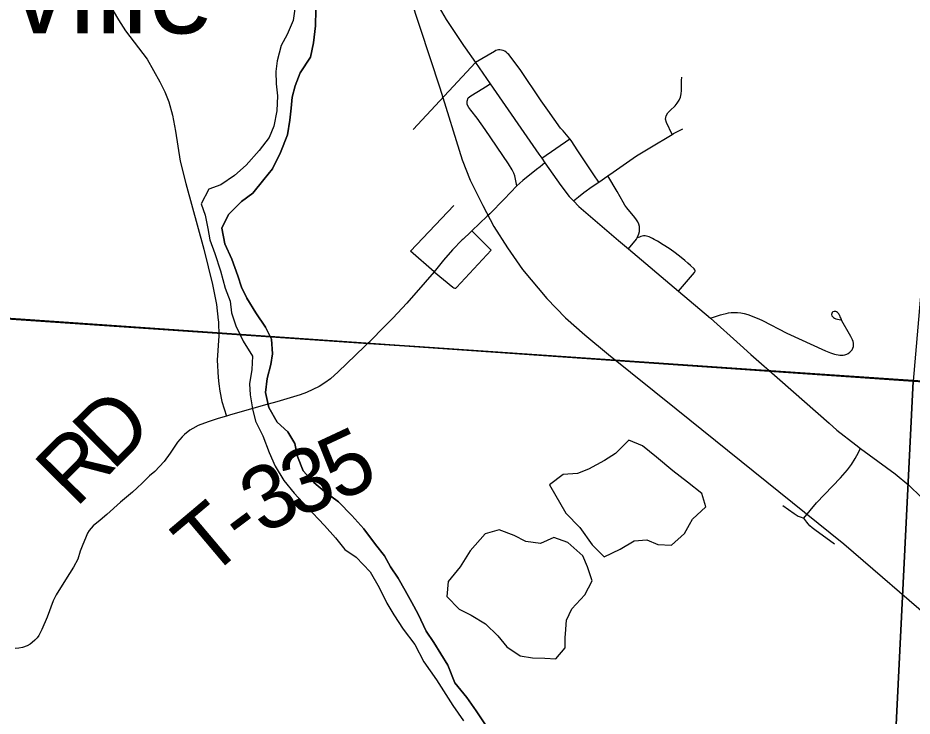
# Model space of a CAD drawing. Extents: x 0 to 34, y 0 to 22.
# Drawn here: x 6.717 to 7.515, y 18.417 to 19.04 of the extents above; entities that cross this region are included whole.
import ezdxf

# ---------------------------------------------------------------- set-up
doc = ezdxf.new("R2010")
doc.units = 0
for name, color, linetype in [('GM_X_Corporation', 7, 'Continuous'), ('GM_X_County_Road', 7, 'Continuous'), ('GM_X_Major_River', 7, 'Continuous'), ('GM_X_Minor_Lake', 7, 'Continuous'), ('GM_X_Rail_Line', 7, 'Continuous'), ('GM_X_Township_Road', 7, 'Continuous'), ('GM_X_Township_Road_Text', 7, 'Continuous'), ('GM_X_Township_Text', 7, 'Continuous'), ('GM_X_Unincorporated_Text', 7, 'Continuous')]:
    doc.layers.add(name, color=color, linetype=linetype)

msp = doc.modelspace()

# ---------------------------------------------------------------- linework, layer by layer
at = {"layer": 'GM_X_Corporation'}
for points in [[(8.9, 18.63104), (8.9, 20.9), (3.64766, 20.9), (3.64639, 20.88271), (3.56651, 19.79699), (3.56604, 19.79055), (3.50701, 18.98834), (4.29309, 18.93502), (4.42098, 18.92635), (4.43616, 18.92532), (5.60032, 18.84635), (6.4706, 18.78732), (6.89502, 18.75853), (7.02554, 18.74968), (7.07142, 18.74657), (7.08445, 18.74568), (7.38896, 18.72502), (7.80881, 18.69655), (7.83532, 18.69516)], [(6.57976, 19.81144), (7.59407, 19.75829), (7.59584, 19.63858), (7.51615, 18.71572), (6.53912, 18.78352)], [(7.51615, 18.71572), (7.4643, 17.67029), (6.43864, 17.7441), (6.53912, 18.78352)], [(8.55257, 18.64968), (8.46287, 17.60104), (7.4643, 17.67029), (7.51615, 18.71572)]]:
    msp.add_lwpolyline(points, close=True, dxfattribs=at)
at = {"layer": 'GM_X_County_Road'}
for points in [[(7.09309, 19.04928), (7.09919, 19.03857), (7.11473, 19.01536), (7.11628, 19.01312), (7.1254, 18.99998), (7.13844, 18.98119), (7.18206, 18.91832), (7.18457, 18.91469), (7.18745, 18.91056), (7.20154, 18.89027), (7.20917, 18.88054), (7.21289, 18.87664), (7.21767, 18.87163), (7.25298, 18.84127), (7.26189, 18.83372), (7.30648, 18.79601), (7.33504, 18.77185), (7.36152, 18.74818), (7.37124, 18.73962), (7.39692, 18.71698)], [(7.39692, 18.71698), (7.44094, 18.67818), (7.44777, 18.67216), (7.46496, 18.65891), (7.46914, 18.65583), (7.49998, 18.63304), (7.512, 18.6231), (7.52321, 18.61225), (7.5399, 18.59374), (7.59634, 18.52742), (7.60398, 18.51724), (7.60691, 18.51305), (7.62242, 18.48872), (7.64954, 18.44339), (7.65833, 18.43067), (7.66812, 18.41872), (7.68735, 18.3985), (7.69979, 18.38557), (7.71323, 18.37161), (7.73813, 18.34329), (7.74385, 18.33657), (7.75408, 18.32513), (7.76217, 18.31591), (7.78442, 18.29052)]]:
    msp.add_lwpolyline(points, dxfattribs=at)
at = {"layer": 'GM_X_Major_River'}
for p, q in [((6.96429, 19.04795), (6.96287, 19.03771)), ((6.98258, 19.03296), (6.98284, 19.04698)), ((6.96287, 19.03771), (6.9573, 19.02515)), ((6.98082, 19.01778), (6.98258, 19.03296)), ((6.9573, 19.02515), (6.95209, 19.01525)), ((6.95209, 19.01525), (6.94842, 19.00157)), ((6.97829, 19.00488), (6.98082, 19.01778)), ((6.94842, 19.00157), (6.94737, 18.99209)), ((6.96895, 18.99077), (6.97829, 19.00488)), ((6.94737, 18.99209), (6.94747, 18.9811)), ((6.96451, 18.97936), (6.96895, 18.99077)), ((6.94747, 18.9811), (6.94869, 18.9705)), ((6.96195, 18.96911), (6.96451, 18.97936)), ((6.94869, 18.9705), (6.94806, 18.95685)), ((6.9609, 18.95924), (6.96195, 18.96911)), ((6.94806, 18.95685), (6.94553, 18.94319)), ((6.95986, 18.94862), (6.9609, 18.95924)), ((6.9577, 18.93572), (6.95986, 18.94862)), ((6.94553, 18.94319), (6.94145, 18.9333)), ((6.95141, 18.91975), (6.9577, 18.93572)), ((6.94145, 18.9333), (6.93247, 18.92147)), ((6.93247, 18.92147), (6.92086, 18.90848)), ((6.94434, 18.90528), (6.95141, 18.91975)), ((6.92086, 18.90848), (6.91034, 18.89929)), ((6.93648, 18.89574), (6.94434, 18.90528)), ((6.91034, 18.89929), (6.89831, 18.89084)), ((6.92675, 18.88352), (6.93648, 18.89574)), ((6.89831, 18.89084), (6.88737, 18.88695)), ((6.88737, 18.88695), (6.88067, 18.87401)), ((6.9166, 18.87623), (6.92675, 18.88352)), ((6.88067, 18.87401), (6.88417, 18.86381)), ((6.90497, 18.86438), (6.9166, 18.87623)), ((6.88417, 18.86381), (6.88654, 18.85208)), ((6.89902, 18.8522), (6.90497, 18.86438)), ((6.88654, 18.85208), (6.88852, 18.84187)), ((6.90179, 18.8382), (6.89902, 18.8522)), ((6.88852, 18.84187), (6.89279, 18.82978)), ((6.90797, 18.82461), (6.90179, 18.8382)), ((6.89279, 18.82978), (6.89784, 18.81429)), ((6.91339, 18.80989), (6.90797, 18.82461)), ((6.89784, 18.81429), (6.90214, 18.79879)), ((6.91651, 18.79968), (6.91339, 18.80989)), ((6.90214, 18.79879), (6.9064, 18.78708)), ((6.92151, 18.78987), (6.91651, 18.79968)), ((6.9064, 18.78708), (6.90763, 18.77686)), ((6.92957, 18.77668), (6.92151, 18.78987)), ((6.90763, 18.77686), (6.91151, 18.76515)), ((6.93801, 18.76388), (6.92957, 18.77668)), ((6.91151, 18.76515), (6.91806, 18.75157)), ((6.9434, 18.75332), (6.93801, 18.76388)), ((6.94427, 18.74006), (6.9434, 18.75332)), ((6.91806, 18.75157), (6.9265, 18.73801)), ((6.9265, 18.73801), (6.92585, 18.72625)), ((6.94284, 18.73057), (6.94427, 18.74006)), ((6.93954, 18.71804), (6.94284, 18.73057)), ((6.92585, 18.72625), (6.92369, 18.71335)), ((6.92369, 18.71335), (6.92453, 18.7035)), ((6.93814, 18.70552), (6.93954, 18.71804)), ((6.9409, 18.69228), (6.93814, 18.70552)), ((6.92453, 18.7035), (6.92654, 18.69102)), ((6.92654, 18.69102), (6.92928, 18.68005)), ((6.94859, 18.67909), (6.9409, 18.69228)), ((6.92928, 18.68005), (6.93583, 18.66685)), ((6.95812, 18.67046), (6.94859, 18.67909)), ((6.93583, 18.66685), (6.94125, 18.65212)), ((6.96426, 18.66029), (6.95812, 18.67046)), ((6.96663, 18.64856), (6.96426, 18.66029)), ((6.94125, 18.65212), (6.94665, 18.64004)), ((6.97167, 18.63572), (6.96663, 18.64856)), ((6.94665, 18.64004), (6.95433, 18.62723)), ((6.98121, 18.6252), (6.97167, 18.63572)), ((6.95433, 18.62723), (6.96351, 18.61594)), ((6.99074, 18.61733), (6.98121, 18.6252)), ((7.00331, 18.60797), (6.99074, 18.61733)), ((6.96351, 18.61594), (6.97497, 18.60354)), ((6.97497, 18.60354), (6.99063, 18.58701)), ((7.01514, 18.59595), (7.00331, 18.60797)), ((7.02584, 18.58392), (7.01514, 18.59595)), ((6.99063, 18.58701), (7.00056, 18.57611)), ((7.03618, 18.56999), (7.02584, 18.58392)), ((7.00056, 18.57611), (7.00898, 18.56558)), ((7.04421, 18.55984), (7.03618, 18.56999)), ((7.00898, 18.56558), (7.01887, 18.55885)), ((7.01887, 18.55885), (7.03147, 18.5457)), ((7.0496, 18.55003), (7.04421, 18.55984)), ((7.03147, 18.5457), (7.03954, 18.53175)), ((7.0565, 18.53986), (7.0496, 18.55003)), ((7.06265, 18.52893), (7.0565, 18.53986)), ((7.03954, 18.53175), (7.04647, 18.51779)), ((7.06879, 18.51838), (7.06265, 18.52893)), ((7.04647, 18.51779), (7.05262, 18.50724)), ((7.07418, 18.50782), (7.06879, 18.51838)), ((7.05262, 18.50724), (7.06106, 18.49443)), ((7.0815, 18.49272), (7.07418, 18.50782)), ((7.06106, 18.49443), (7.07139, 18.48089)), ((7.0884, 18.48256), (7.0815, 18.49272)), ((7.07139, 18.48089), (7.07947, 18.46542)), ((7.10069, 18.46221), (7.0884, 18.48256)), ((7.07947, 18.46542), (7.09058, 18.44923)), ((7.10688, 18.44672), (7.10069, 18.46221)), ((7.09058, 18.44923), (7.09902, 18.43604)), ((7.11759, 18.43356), (7.10688, 18.44672)), ((7.09902, 18.43604), (7.10516, 18.42625)), ((7.12601, 18.42151), (7.11759, 18.43356)), ((7.10516, 18.42625), (7.11474, 18.41269)), ((7.13483, 18.40833), (7.12601, 18.42151))]:
    msp.add_line(p, q, dxfattribs=at)
for points in [[(6.96429, 19.04795), (6.96287, 19.03771), (6.9573, 19.02515), (6.95209, 19.01525), (6.94842, 19.00157)], [(6.98284, 19.04698), (6.98258, 19.03296), (6.98082, 19.01778), (6.97829, 19.00488), (6.96895, 18.99077)], [(6.94842, 19.00157), (6.94737, 18.99209), (6.94747, 18.9811), (6.94869, 18.9705), (6.94806, 18.95685), (6.94553, 18.94319), (6.94145, 18.9333), (6.93247, 18.92147), (6.92086, 18.90848), (6.91034, 18.89929), (6.89831, 18.89084), (6.88737, 18.88695), (6.88067, 18.87401), (6.88417, 18.86381), (6.88654, 18.85208), (6.88852, 18.84187), (6.89279, 18.82978), (6.89784, 18.81429), (6.90214, 18.79879), (6.9064, 18.78708), (6.90763, 18.77686), (6.91151, 18.76515), (6.91806, 18.75157), (6.9265, 18.73801), (6.92585, 18.72625), (6.92369, 18.71335), (6.92453, 18.7035), (6.92654, 18.69102), (6.92928, 18.68005), (6.93583, 18.66685), (6.94125, 18.65212), (6.94665, 18.64004), (6.95433, 18.62723), (6.96351, 18.61594), (6.97497, 18.60354), (6.99063, 18.58701), (7.00056, 18.57611), (7.00898, 18.56558), (7.01887, 18.55885), (7.03147, 18.5457), (7.03954, 18.53175), (7.04647, 18.51779), (7.05262, 18.50724), (7.06106, 18.49443), (7.07139, 18.48089), (7.07947, 18.46542), (7.09058, 18.44923), (7.09902, 18.43604), (7.10516, 18.42625), (7.11474, 18.41269)], [(6.96895, 18.99077), (6.96451, 18.97936), (6.96195, 18.96911), (6.9609, 18.95924), (6.95986, 18.94862), (6.9577, 18.93572), (6.95141, 18.91975), (6.94434, 18.90528), (6.93648, 18.89574), (6.92675, 18.88352), (6.9166, 18.87623), (6.90497, 18.86438), (6.89902, 18.8522), (6.90179, 18.8382), (6.90797, 18.82461), (6.91339, 18.80989), (6.91651, 18.79968), (6.92151, 18.78987), (6.92957, 18.77668), (6.93801, 18.76388), (6.9434, 18.75332), (6.94427, 18.74006), (6.94284, 18.73057), (6.93954, 18.71804), (6.93814, 18.70552), (6.9409, 18.69228), (6.94859, 18.67909), (6.95812, 18.67046), (6.96426, 18.66029), (6.96663, 18.64856), (6.97167, 18.63572), (6.98121, 18.6252), (6.99074, 18.61733), (7.00331, 18.60797), (7.01514, 18.59595), (7.02584, 18.58392), (7.03618, 18.56999), (7.04421, 18.55984), (7.0496, 18.55003), (7.0565, 18.53986), (7.06265, 18.52893), (7.06879, 18.51838), (7.07418, 18.50782), (7.0815, 18.49272), (7.0884, 18.48256), (7.10069, 18.46221), (7.10688, 18.44672), (7.11759, 18.43356), (7.12601, 18.42151), (7.13483, 18.40833)]]:
    msp.add_lwpolyline(points, dxfattribs=at)
at = {"layer": 'GM_X_Minor_Lake'}
for p, q in [((7.26239, 18.663), (7.25039, 18.65115)), ((7.27454, 18.65819), (7.26239, 18.663)), ((7.28712, 18.64807), (7.27454, 18.65819)), ((7.25039, 18.65115), (7.2406, 18.645)), ((7.2406, 18.645), (7.22629, 18.63729)), ((7.3016, 18.6357), (7.28712, 18.64807)), ((7.20363, 18.63253), (7.1916, 18.62333)), ((7.21649, 18.63341), (7.20363, 18.63253)), ((7.22629, 18.63729), (7.21649, 18.63341)), ((7.31456, 18.62559), (7.3016, 18.6357)), ((7.32751, 18.61547), (7.31456, 18.62559)), ((7.1916, 18.62333), (7.2062, 18.59807)), ((7.33102, 18.60376), (7.32751, 18.61547)), ((7.31901, 18.59266), (7.33102, 18.60376)), ((7.2062, 18.59807), (7.21842, 18.5853)), ((7.31635, 18.5878), (7.31901, 18.59266)), ((7.21842, 18.5853), (7.22953, 18.56986)), ((7.31193, 18.57971), (7.31635, 18.5878)), ((7.13409, 18.5796), (7.12061, 18.56432)), ((7.14655, 18.58313), (7.13409, 18.5796)), ((7.15984, 18.57794), (7.14655, 18.58313)), ((7.17048, 18.57274), (7.15984, 18.57794)), ((7.19542, 18.57637), (7.18336, 18.57096)), ((7.20795, 18.57194), (7.19542, 18.57637)), ((7.30029, 18.56937), (7.31193, 18.57971)), ((7.18336, 18.57096), (7.17048, 18.57274)), ((7.22129, 18.55994), (7.20795, 18.57194)), ((7.22953, 18.56986), (7.24022, 18.55897)), ((7.25454, 18.56592), (7.26696, 18.57324)), ((7.26696, 18.57324), (7.2783, 18.5741)), ((7.2783, 18.5741), (7.28818, 18.57002)), ((7.28818, 18.57002), (7.30029, 18.56937)), ((7.12061, 18.56432), (7.11165, 18.55022)), ((7.24022, 18.55897), (7.25454, 18.56592)), ((7.22554, 18.55012), (7.22129, 18.55994)), ((7.11165, 18.55022), (7.10117, 18.53686)), ((7.22943, 18.53765), (7.22554, 18.55012)), ((7.10117, 18.53686), (7.09977, 18.52359)), ((7.22311, 18.52509), (7.22943, 18.53765)), ((7.09977, 18.52359), (7.11084, 18.51232)), ((7.21149, 18.51248), (7.22311, 18.52509)), ((7.11084, 18.51232), (7.12148, 18.50711)), ((7.12148, 18.50711), (7.13442, 18.49927)), ((7.20666, 18.50258), (7.21149, 18.51248)), ((7.13442, 18.49927), (7.14548, 18.48838)), ((7.20563, 18.49045), (7.20666, 18.50258)), ((7.20555, 18.48702), (7.20563, 18.49045)), ((7.14548, 18.48838), (7.15352, 18.4786)), ((7.20536, 18.47794), (7.20555, 18.48702)), ((7.15352, 18.4786), (7.16531, 18.47075)), ((7.19712, 18.46801), (7.20536, 18.47794)), ((7.16531, 18.47075), (7.1763, 18.46896)), ((7.1763, 18.46896), (7.18728, 18.46868)), ((7.18728, 18.46868), (7.19712, 18.46801))]:
    msp.add_line(p, q, dxfattribs=at)
at = {"layer": 'GM_X_Rail_Line'}
msp.add_lwpolyline([(6.98662, 19.30256), (7.09368, 18.9774), (7.11355, 18.91342), (7.12056, 18.89504), (7.13192, 18.8725), (7.14183, 18.85389), (7.15398, 18.83476), (7.1673, 18.81542), (7.18918, 18.78941), (7.20588, 18.7724), (7.2229, 18.75718), (7.24425, 18.73963), (7.30439, 18.69111), (7.45417, 18.57062), (7.53827, 18.49802)], dxfattribs=at)
at = {"layer": 'GM_X_Township_Road'}
msp.add_line((7.06989, 18.94023), (7.1254, 18.99998), dxfattribs=at)
for points in [[(6.79658, 19.05606), (6.80704, 19.03811), (6.81312, 19.02851), (6.83249, 19.00318), (6.8438, 18.98288), (6.84829, 18.97389), (6.85176, 18.96512), (6.85513, 18.95324), (6.85784, 18.93871), (6.86199, 18.91219), (6.86692, 18.89202), (6.88295, 18.83345), (6.89091, 18.80193), (6.89431, 18.78419), (6.89588, 18.77028), (6.89608, 18.76857), (6.89643, 18.75616), (6.89505, 18.73458), (6.89583, 18.71909), (6.89649, 18.71342)], [(7.18457, 18.91469), (7.20951, 18.93191), (7.20354, 18.9392), (7.20139, 18.94148), (7.1901, 18.9575), (7.18419, 18.96582), (7.16539, 18.99391), (7.15513, 19.00714), (7.15407, 19.00825), (7.1529, 19.00927), (7.15157, 19.01015), (7.15004, 19.0108), (7.14853, 19.01125), (7.14724, 19.01144), (7.14597, 19.01148), (7.14481, 19.01125), (7.14367, 19.01075), (7.14234, 19.01005), (7.1254, 18.99998)], [(7.30102, 18.93602), (7.29578, 18.94665), (7.29512, 18.94962), (7.29559, 18.95257), (7.29717, 18.95515), (7.2992, 18.9574), (7.30358, 18.96159), (7.30553, 18.96387), (7.30709, 18.96644), (7.30826, 18.9692), (7.30895, 18.97212), (7.30919, 18.97511), (7.30931, 18.98414), (7.30952, 18.98715)], [(7.16245, 18.89016), (7.16054, 18.89885), (7.15966, 18.9013), (7.15808, 18.90446), (7.15488, 18.90971), (7.13404, 18.94025), (7.12699, 18.95032), (7.12118, 18.9575), (7.11943, 18.96004), (7.11815, 18.96276), (7.11791, 18.9657), (7.11901, 18.96854), (7.12134, 18.97053), (7.13186, 18.97694), (7.13435, 18.97855), (7.13844, 18.98119)], [(7.21289, 18.87664), (7.21728, 18.88025), (7.22205, 18.88419), (7.22968, 18.88946), (7.23539, 18.89341), (7.24347, 18.89902), (7.24819, 18.90226), (7.26922, 18.91694), (7.28095, 18.92398), (7.30102, 18.93602), (7.30215, 18.93671), (7.30761, 18.93959), (7.3104, 18.9409)], [(7.23539, 18.89341), (7.23098, 18.89983), (7.21672, 18.92116), (7.21085, 18.9304), (7.20951, 18.93191)], [(7.18745, 18.91056), (7.1831, 18.90713), (7.1799, 18.90459), (7.16773, 18.89492), (7.16245, 18.89016), (7.15103, 18.87825), (7.13813, 18.86507)], [(7.26189, 18.83372), (7.26901, 18.84252), (7.26977, 18.84368), (7.27129, 18.8473), (7.27169, 18.84943), (7.27189, 18.85181), (7.27169, 18.85393), (7.27124, 18.85591), (7.27027, 18.85803), (7.26921, 18.85975), (7.26769, 18.86188), (7.26046, 18.87048), (7.25871, 18.87283), (7.25718, 18.87536), (7.25173, 18.88497), (7.24347, 18.89902)], [(7.08843, 18.81339), (7.06758, 18.83165), (7.10606, 18.87244)], [(7.13813, 18.86507), (7.13598, 18.86287), (7.12221, 18.84986), (7.12093, 18.84865), (7.11438, 18.84246)], [(7.08843, 18.81339), (7.10524, 18.79978), (7.10624, 18.79896), (7.10696, 18.79861), (7.10798, 18.7987), (7.10865, 18.79921), (7.13957, 18.83262), (7.12223, 18.84983)], [(7.11438, 18.84246), (7.11365, 18.84178), (7.10501, 18.83302), (7.0968, 18.8238), (7.08843, 18.81339), (7.08069, 18.80415), (7.06433, 18.78552), (7.05162, 18.77187), (7.04196, 18.76216)], [(7.30648, 18.79601), (7.32093, 18.81259), (7.32132, 18.81323), (7.32144, 18.81388), (7.32134, 18.81454), (7.32107, 18.81516), (7.32049, 18.81598), (7.31736, 18.81906), (7.31507, 18.82106), (7.31211, 18.82352), (7.30737, 18.82724), (7.30237, 18.83108), (7.29815, 18.83412), (7.29288, 18.83757), (7.28784, 18.84057), (7.28487, 18.84227), (7.28328, 18.84312), (7.28208, 18.84375), (7.28051, 18.84447), (7.27929, 18.84493), (7.27796, 18.84526), (7.27677, 18.84542), (7.2755, 18.84542), (7.27424, 18.84523), (7.27302, 18.84487), (7.27178, 18.84434), (7.26977, 18.84368)], [(7.33504, 18.77185), (7.34406, 18.77488), (7.34654, 18.77561), (7.34919, 18.77629), (7.35132, 18.77671), (7.35367, 18.77697), (7.3567, 18.77714), (7.3593, 18.7771), (7.36216, 18.77684), (7.36511, 18.7762), (7.36835, 18.77518), (7.37831, 18.77134), (7.38152, 18.76993), (7.40315, 18.75872), (7.43769, 18.74285), (7.44237, 18.741), (7.44585, 18.73992), (7.44732, 18.73953), (7.44898, 18.73918), (7.45045, 18.73899), (7.45186, 18.7389), (7.45341, 18.73896), (7.45492, 18.73913), (7.45668, 18.73976), (7.45808, 18.74056), (7.45955, 18.74164), (7.46078, 18.74277), (7.46169, 18.74386), (7.46229, 18.74514), (7.46266, 18.7467), (7.46274, 18.74805), (7.46262, 18.74953), (7.46233, 18.75115), (7.4619, 18.75257), (7.46129, 18.75397), (7.46038, 18.7556), (7.45914, 18.75779), (7.45228, 18.76974), (7.45192, 18.77058), (7.45164, 18.77137), (7.45133, 18.77223), (7.45099, 18.77317), (7.45053, 18.77425), (7.4501, 18.77505), (7.4496, 18.77578), (7.44909, 18.77637), (7.44856, 18.77692), (7.4477, 18.77759), (7.44705, 18.77783), (7.44648, 18.77798), (7.44539, 18.778), (7.4444, 18.77757), (7.44376, 18.77692), (7.4434, 18.77619), (7.44327, 18.77517), (7.4435, 18.7742), (7.44398, 18.77341), (7.44478, 18.77254), (7.44577, 18.7719), (7.44709, 18.77133), (7.44837, 18.77097), (7.44994, 18.77075), (7.4514, 18.77061)], [(7.04196, 18.76216), (7.04127, 18.76147), (7.03413, 18.75428), (7.00297, 18.72405), (6.99595, 18.71796), (6.99098, 18.71431), (6.98584, 18.71112), (6.9804, 18.70826)], [(6.89649, 18.71342), (6.89725, 18.70679), (6.8991, 18.69771), (6.9032, 18.68465)], [(6.9804, 18.70826), (6.97474, 18.70577), (6.9689, 18.70365), (6.94813, 18.69741), (6.93606, 18.69403), (6.90587, 18.68541), (6.9032, 18.68465), (6.89582, 18.68254), (6.8868, 18.67959), (6.87796, 18.67614), (6.87314, 18.6736), (6.87057, 18.67193), (6.86577, 18.66815), (6.86357, 18.66603), (6.8615, 18.66377), (6.85959, 18.66133), (6.85303, 18.6516), (6.84764, 18.64413), (6.8436, 18.63949), (6.83928, 18.63511), (6.8346, 18.63118), (6.82789, 18.62471), (6.82356, 18.62053), (6.81942, 18.61685), (6.80882, 18.60768), (6.79663, 18.59683), (6.79041, 18.59165), (6.78437, 18.58682), (6.78068, 18.58242), (6.77918, 18.58001), (6.7779, 18.57727), (6.77436, 18.56842), (6.7728, 18.56398), (6.77052, 18.55699), (6.76687, 18.5498), (6.75956, 18.53839), (6.75136, 18.52513), (6.74859, 18.51981), (6.74315, 18.50524), (6.73855, 18.49412), (6.73571, 18.48876), (6.73435, 18.48684), (6.73232, 18.48466), (6.72999, 18.48245), (6.72814, 18.48098), (6.72534, 18.47962), (6.72114, 18.47811), (6.71786, 18.4776), (6.71478, 18.47736)], [(7.44574, 18.57038), (7.42818, 18.58311), (7.42584, 18.58497), (7.42393, 18.58662), (7.42227, 18.58847), (7.42109, 18.58989), (7.42009, 18.5912), (7.41841, 18.59342), (7.42988, 18.60712), (7.45118, 18.62958), (7.45728, 18.63657), (7.46104, 18.64148), (7.46436, 18.64669), (7.46579, 18.64943), (7.46914, 18.65583)], [(7.3996, 18.60497), (7.40971, 18.59778), (7.41351, 18.5954), (7.41508, 18.59459), (7.41841, 18.59342)]]:
    msp.add_lwpolyline(points, dxfattribs=at)
at = {"layer": 'GM_X_Township_Text'}
msp.add_lwpolyline([(8.9, 18.63104), (7.83532, 18.69516), (7.80881, 18.69655), (7.38896, 18.72502), (7.08445, 18.74568), (7.07142, 18.74657), (7.02554, 18.74968), (6.89502, 18.75853), (6.4706, 18.78732), (5.60032, 18.84635), (4.43616, 18.92532), (4.42098, 18.92635), (4.29309, 18.93502), (3.50701, 18.98834), (3.39511, 17.26162), (3.35157, 16.58978), (3.30586, 15.8844), (3.28444, 15.55396), (3.23387, 14.77351), (3.19187, 14.12547), (3.19022, 14.1)], dxfattribs=at)

# ---------------------------------------------------------------- texts
at = {"layer": 'GM_X_Township_Road_Text'}
for s, rotation, p in [('D', 44.86347, (6.80144, 18.63505)), ('5', 25.0576, (7.00299, 18.60773)), ('R', 45.356, (6.76874, 18.60194)), ('3', 19.52779, (6.96447, 18.59377)), ('3', 27.86372, (6.93553, 18.57829)), ('T', 40.14576, (6.887, 18.53874)), ('-', 36.70752, (6.91878, 18.56558))]:
    msp.add_text(s, height=0.05682, rotation=rotation, dxfattribs=at).set_placement(p)
at = {"layer": 'GM_X_Unincorporated_Text'}
msp.add_text('Haydenville', height=0.0789773, rotation=0.00001, dxfattribs=at).set_placement((6.3463, 19.0262))

doc.saveas('drawing.dxf')
